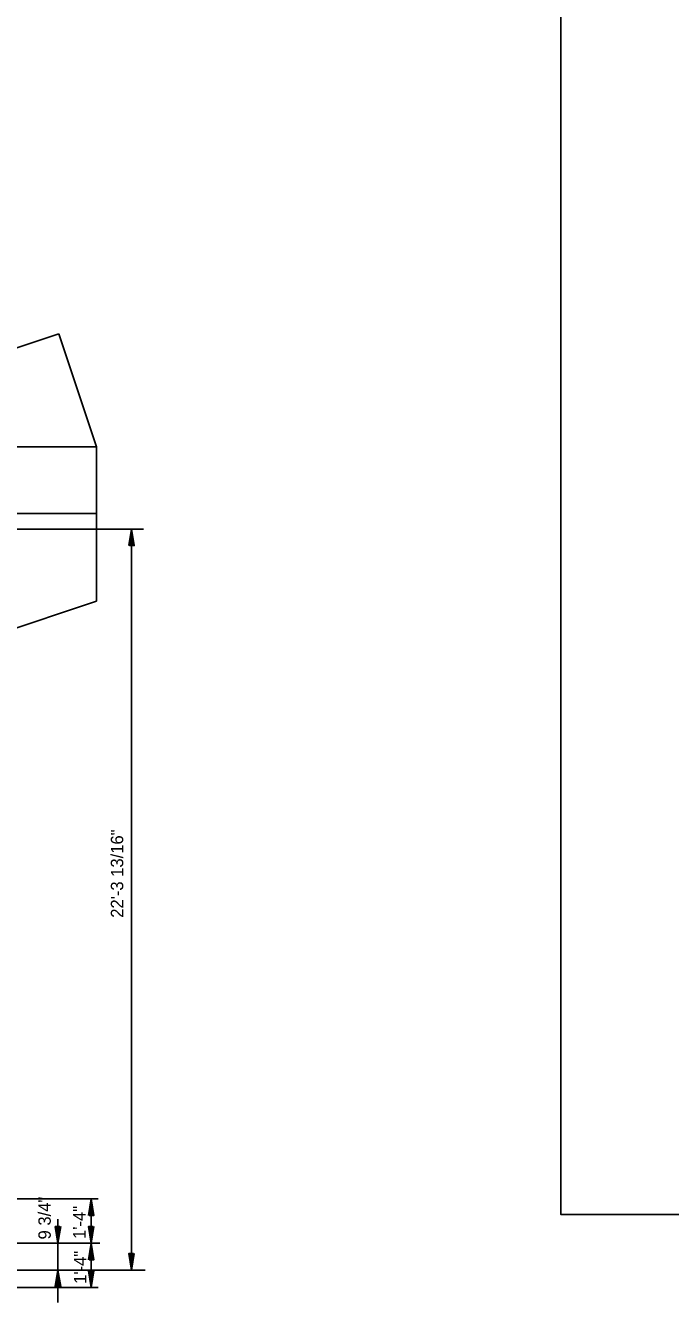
# Model space of a CAD drawing. Extents: x -48 to 108, y -5 to 100.
# Drawn here: x -14.84 to 4.59, y -1.36 to 37.1 of the extents above; entities that cross this region are included whole.
import ezdxf

# ---------------------------------------------------------------- set-up
doc = ezdxf.new("R2010")
doc.units = 0
for name, color, linetype in [('Level 1', 7, 'Continuous'), ('Level 25', 7, 'Continuous'), ('Level 50', 7, 'Continuous')]:
    doc.layers.add(name, color=color, linetype=linetype)

msp = doc.modelspace()

# ---------------------------------------------------------------- linework, layer by layer
at = {"layer": 'Level 1'}
msp.add_lwpolyline([(1.292, 75.958), (107.958, 75.958), (107.958, 1.292), (1.292, 1.292)], close=True, dxfattribs=at)
at = {"layer": 'Level 25'}
for p, q in [((-13.837, 27.814), (-39.056, 19.408)), ((-13.837, 27.814), (-12.701, 24.408)), ((-18.056, 24.408), (-12.701, 24.408)), ((-12.701, 19.76), (-12.701, 24.408)), ((-17.146, 22.408), (-12.701, 22.408)), ((-16.907, 21.936), (-11.283, 21.936)), ((-11.649, -0.381), (-11.649, 21.936)), ((-12.701, 19.76), (-39.056, 10.975)), ((-16.864, 1.765), (-12.651, 1.765)), ((-12.864, 1.765), (-12.864, 0.431)), ((-13.864, 1.154), (-13.864, 0.431)), ((-18.304, 0.431), (-12.605, 0.431)), ((-13.864, 0.431), (-13.865, -0.381)), ((-12.864, 0.431), (-12.865, -0.903)), ((-16.909, -0.381), (-13.64, -0.381)), ((-13.865, -0.381), (-13.865, -1.356)), ((-13.64, -0.381), (-11.237, -0.381)), ((-16.865, -0.902), (-12.651, -0.902))]:
    msp.add_line(p, q, dxfattribs=at)
at = {"layer": 'Level 50'}
for p, q in [((-11.649, 21.936), (-11.649, 21.936)), ((-11.649, 21.798), (-11.649, 21.798)), ((-12.864, 1.765), (-12.864, 1.765)), ((-12.864, 1.626), (-12.864, 1.626)), ((-13.864, 0.57), (-13.864, 0.57)), ((-13.864, 0.431), (-13.864, 0.431)), ((-12.864, 0.569), (-12.864, 0.569)), ((-12.864, 0.431), (-12.864, 0.431)), ((-12.864, 0.431), (-12.864, 0.431)), ((-12.864, 0.292), (-12.864, 0.292)), ((-13.865, -0.381), (-13.865, -0.381)), ((-11.649, -0.243), (-11.649, -0.243)), ((-11.649, -0.381), (-11.649, -0.381)), ((-13.865, -0.52), (-13.865, -0.52)), ((-12.865, -0.764), (-12.865, -0.764)), ((-12.865, -0.903), (-12.865, -0.903))]:
    msp.add_line(p, q, dxfattribs=at)
for points in [[(-11.732, 21.438), (-11.649, 21.936), (-11.566, 21.438), (-11.708, 21.438), (-11.649, 21.798), (-11.593, 21.459), (-11.684, 21.459), (-11.649, 21.664), (-11.62, 21.48), (-11.657, 21.48), (-11.649, 21.526)], [(-12.947, 1.266), (-12.864, 1.765), (-12.782, 1.266), (-12.923, 1.266), (-12.864, 1.626), (-12.808, 1.287), (-12.899, 1.287), (-12.864, 1.493), (-12.835, 1.309), (-12.872, 1.309), (-12.864, 1.354)], [(-13.782, 0.93), (-13.864, 0.431), (-13.947, 0.93), (-13.806, 0.93), (-13.864, 0.57), (-13.92, 0.908), (-13.83, 0.908), (-13.864, 0.703), (-13.894, 0.887), (-13.856, 0.887), (-13.864, 0.842)], [(-12.782, 0.929), (-12.864, 0.431), (-12.947, 0.93), (-12.806, 0.929), (-12.864, 0.569), (-12.92, 0.908), (-12.83, 0.908), (-12.864, 0.703), (-12.894, 0.887), (-12.856, 0.887), (-12.864, 0.841)], [(-12.947, -0.068), (-12.864, 0.431), (-12.782, -0.068), (-12.923, -0.068), (-12.864, 0.292), (-12.809, -0.047), (-12.899, -0.047), (-12.864, 0.159), (-12.835, -0.025), (-12.873, -0.025), (-12.864, 0.02)], [(-11.566, 0.117), (-11.649, -0.381), (-11.732, 0.117), (-11.59, 0.117), (-11.649, -0.243), (-11.705, 0.096), (-11.614, 0.096), (-11.649, -0.109), (-11.678, 0.075), (-11.641, 0.075), (-11.649, 0.029)], [(-13.947, -0.88), (-13.865, -0.381), (-13.782, -0.88), (-13.923, -0.88), (-13.865, -0.52), (-13.809, -0.859), (-13.899, -0.859), (-13.865, -0.653), (-13.835, -0.837), (-13.873, -0.837), (-13.865, -0.792)], [(-12.782, -0.404), (-12.865, -0.903), (-12.947, -0.404), (-12.806, -0.404), (-12.865, -0.764), (-12.921, -0.425), (-12.83, -0.425), (-12.865, -0.631), (-12.894, -0.447), (-12.857, -0.447), (-12.865, -0.492)]]:
    msp.add_lwpolyline(points, dxfattribs=at)

# ---------------------------------------------------------------- texts
at = {"layer": 'Level 25'}
for s, height, p in [('22\'-3 13/16"', 0.37333, (-11.897, 10.229)), ('9 3/4"', 0.3733, (-14.08, 0.541)), ('1\'-4"', 0.3733, (-13.033, 0.556)), ('1\'-4"', 0.3733, (-13.009, -0.794))]:
    msp.add_text(s, height=height, rotation=90, dxfattribs=at).set_placement(p)

doc.saveas('drawing.dxf')
